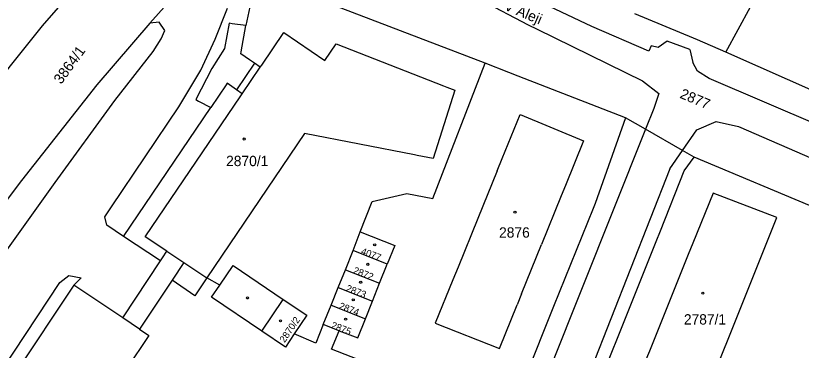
# Model space of a CAD drawing. Extents: x -527335 to -526256, y -1079142 to -1077809.
# Drawn here: x -527020.7 to -526891.4, y -1078778.8 to -1078723.7 of the extents above; entities that cross this region are included whole.
import ezdxf

# ---------------------------------------------------------------- set-up
doc = ezdxf.new("R2010")
doc.units = 0
for name, color, linetype in [('Vrstva 1', 7, 'Continuous'), ('Vrstva 2', 7, 'Continuous'), ('Vrstva 4', 7, 'Continuous'), ('Vrstva 5', 7, 'Continuous'), ('Vrstva 7', 7, 'Continuous')]:
    doc.layers.add(name, color=color, linetype=linetype)

msp = doc.modelspace()

# ---------------------------------------------------------------- linework, layer by layer
at = {"layer": 'Vrstva 1'}
for p, q in [((-526980.85, -1078705.02), (-526998.63, -1078724.92)), ((-526880.94, -1078739.86), (-526903.84, -1078729.73)), ((-526881.96, -1078758.41), (-526909.05, -1078746.98)), ((-526965.19, -1078762.39), (-526964, -1078759.32)), ((-526966.46, -1078765.55), (-526965.19, -1078762.39)), ((-526959.56, -1078764.61), (-526965.19, -1078762.39)), ((-526967.65, -1078768.49), (-526966.46, -1078765.55)), ((-526966.46, -1078765.55), (-526960.82, -1078767.77)), ((-526960.82, -1078767.77), (-526959.56, -1078764.61)), ((-526962, -1078770.71), (-526960.82, -1078767.77)), ((-526968.81, -1078771.4), (-526967.65, -1078768.49)), ((-526967.65, -1078768.49), (-526962, -1078770.71)), ((-526963.17, -1078773.62), (-526962, -1078770.71)), ((-526970.1, -1078774.59), (-526968.81, -1078771.4)), ((-526968.81, -1078771.4), (-526963.17, -1078773.62)), ((-527000.35, -1078775.31), (-527003.07, -1078773.49)), ((-526967.47, -1078775.61), (-526970.1, -1078774.59))]:
    msp.add_line(p, q, dxfattribs=at)
for points in [[(-527072.22, -1078805.43), (-527063.35, -1078791.03), (-527051.39, -1078772.86), (-527021.8, -1078732.24), (-527016.31, -1078725.38), (-526999.22, -1078705.77), (-526979.26, -1078684.5), (-526961.36, -1078666.17), (-526945.34, -1078649.61), (-526932.24, -1078641.62), (-526929.63, -1078639.61), (-526929.14, -1078637.23), (-526930.46, -1078635.68), (-526927.65, -1078633), (-526895.17, -1078602.34)], [(-526943.47, -1078731.53), (-526981.07, -1078717.06), (-526983.77, -1078716), (-526980.85, -1078705.02)], [(-526903.84, -1078729.73), (-526895.72, -1078714.74), (-526874.21, -1078723.48)], [(-526903.84, -1078729.73), (-526908.52, -1078727.66), (-526909.18, -1078727.41), (-526918.83, -1078723.42)], [(-526998.63, -1078724.92), (-527007.36, -1078735.07), (-527019.76, -1078750.86), (-527025.21, -1078757.99), (-527037.26, -1078775.41), (-527043.97, -1078785.5), (-527052.05, -1078797.8), (-527057.33, -1078806.06), (-527064.89, -1078818.36), (-527077.97, -1078839.97), (-527106.45, -1078888.73), (-527179.38, -1079013.92), (-527179.74, -1079015.3)], [(-527060.55, -1078815.59), (-527054.66, -1078805.64), (-527050.43, -1078799.71), (-527048.56, -1078798.89), (-527046.8, -1078797.42), (-527041.37, -1078789.55), (-527032.93, -1078777.37), (-527021.38, -1078761.15), (-527014.2, -1078751.18), (-527004.39, -1078737.66), (-526998.1, -1078729.59), (-526996.78, -1078727.49), (-526996.17, -1078726.12), (-526997.1, -1078724.79), (-526998.63, -1078724.92)], [(-526964, -1078759.32), (-526962.06, -1078754.32), (-526956.34, -1078752.97), (-526952.04, -1078753.82), (-526943.47, -1078731.53)], [(-526920.35, -1078740.55), (-526938, -1078733.66), (-526939.57, -1078733.05), (-526943.47, -1078731.53)], [(-526920.35, -1078740.55), (-526925.32, -1078754.62), (-526925.68, -1078755.46), (-526932.2, -1078771.6), (-526932.87, -1078773.24), (-526939.55, -1078790.03)], [(-526909.05, -1078746.98), (-526910.94, -1078745.91), (-526917.07, -1078742.42), (-526920.35, -1078740.55)], [(-526927.47, -1078791.39), (-526922.47, -1078778.85), (-526921.77, -1078777.09), (-526915.3, -1078760.88), (-526914.6, -1078759.12), (-526910.68, -1078749.28), (-526909.05, -1078746.98)], [(-526920.46, -1078789.01), (-526909.97, -1078793.22), (-526902.69, -1078775.08), (-526895.42, -1078756.95), (-526905.94, -1078752.92), (-526909.26, -1078761.18), (-526910.01, -1078763.03), (-526913.2, -1078770.97), (-526916.41, -1078778.95), (-526917.14, -1078780.77), (-526920.46, -1078789.01)], [(-526964, -1078759.32), (-526958.34, -1078761.55), (-526959.56, -1078764.61)], [(-526980.2, -1078775.69), (-526988.47, -1078770.08), (-526987.11, -1078768.1), (-526989.28, -1078766.89), (-526991.26, -1078769.82), (-526994.98, -1078767.27), (-527000.35, -1078775.31)], [(-527003.07, -1078773.49), (-527011.16, -1078768.09), (-527030.63, -1078797.3), (-527031.8, -1078796.49), (-527033.21, -1078798.48), (-527034.85, -1078797.32), (-527038.02, -1078801.77), (-527036.37, -1078802.94), (-527037.76, -1078804.91), (-527032.72, -1078808.35), (-527034.82, -1078811.52), (-527030.31, -1078814.54), (-527028.85, -1078818), (-527029.14, -1078824.18), (-527031.1, -1078828.29)], [(-526980.2, -1078775.69), (-526976.67, -1078770.44), (-526972.82, -1078773.04), (-526974.87, -1078776.13)], [(-526970.1, -1078774.59), (-526971.32, -1078777.62), (-526974.87, -1078776.13)], [(-526967.47, -1078775.61), (-526964.43, -1078776.78), (-526963.17, -1078773.62)], [(-526974.87, -1078776.13), (-526976.32, -1078778.32), (-526980.2, -1078775.69)], [(-526959.04, -1078782.42), (-526968.73, -1078778.63), (-526967.47, -1078775.61)]]:
    msp.add_lwpolyline(points, dxfattribs=at)
at = {"layer": 'Vrstva 4'}
for p, q in [((-526981.07, -1078717.06), (-526982.85, -1078725.3)), ((-526944.09, -1078721.15), (-526936.39, -1078725.2)), ((-526925.87, -1078725.49), (-526935.89, -1078720.7)), ((-526987.91, -1078727.56), (-526985.84, -1078722.46)), ((-526985.57, -1078724.93), (-526986.36, -1078729.12)), ((-526985.08, -1078725.03), (-526985.57, -1078724.93)), ((-526982.85, -1078725.3), (-526985.08, -1078725.03)), ((-526983.59, -1078729.63), (-526982.85, -1078725.3)), ((-526936.39, -1078725.2), (-526934.89, -1078725.91)), ((-526916.5, -1078729.56), (-526925.87, -1078725.49)), ((-526980.23, -1078731.87), (-526976.56, -1078726.47)), ((-526976.56, -1078726.47), (-526969.86, -1078731.1)), ((-526934.89, -1078725.91), (-526917.53, -1078734.45)), ((-526990.26, -1078732.7), (-526987.91, -1078727.56)), ((-526913.47, -1078727.92), (-526914.99, -1078728.96)), ((-526909.76, -1078729.27), (-526913.47, -1078727.92)), ((-526986.36, -1078729.12), (-526988.44, -1078732.41)), ((-526969.86, -1078731.1), (-526967.95, -1078728.34)), ((-526967.95, -1078728.34), (-526950.3, -1078735.25)), ((-526916.1, -1078728.68), (-526916.5, -1078729.56)), ((-526914.99, -1078728.96), (-526916.1, -1078728.68)), ((-526909.76, -1078729.27), (-526909.25, -1078731.41)), ((-526983.65, -1078730.01), (-526983.59, -1078729.63)), ((-526982.22, -1078730.99), (-526983.65, -1078730.01)), ((-526981.41, -1078731.55), (-526984.39, -1078735.92)), ((-526981.41, -1078731.55), (-526982.22, -1078730.99)), ((-526980.46, -1078732.2), (-526981.41, -1078731.55)), ((-526980.46, -1078732.2), (-526980.23, -1078731.87)), ((-526908.48, -1078732.83), (-526909.25, -1078731.41)), ((-526993.89, -1078738.73), (-526990.26, -1078732.7)), ((-526988.44, -1078732.41), (-526991.09, -1078737.5)), ((-526983.44, -1078736.59), (-526980.46, -1078732.2)), ((-526906.55, -1078734.05), (-526908.48, -1078732.83)), ((-526917.53, -1078734.45), (-526914.87, -1078736.51)), ((-526868.74, -1078750.29), (-526906.55, -1078734.05)), ((-526986.1, -1078735.07), (-526988.62, -1078738.81)), ((-526985.93, -1078734.82), (-526986.1, -1078735.07)), ((-526984.39, -1078735.92), (-526985.93, -1078734.82)), ((-526983.44, -1078736.59), (-526984.39, -1078735.92)), ((-526948.45, -1078735.98), (-526951.99, -1078747.23)), ((-526950.3, -1078735.25), (-526949.75, -1078735.47)), ((-526949.75, -1078735.47), (-526948.45, -1078735.98)), ((-526999.41, -1078760.11), (-526983.66, -1078736.92)), ((-526983.66, -1078736.92), (-526983.44, -1078736.59)), ((-526914.87, -1078736.51), (-526915.7, -1078739)), ((-526991.09, -1078737.5), (-526990.61, -1078737.76)), ((-526990.61, -1078737.76), (-526988.62, -1078738.81)), ((-527004.94, -1078755.16), (-526993.89, -1078738.73)), ((-527002.98, -1078760.08), (-526988.62, -1078738.81)), ((-526915.7, -1078739), (-526917.07, -1078742.42)), ((-526940.65, -1078747.23), (-526937.69, -1078739.96)), ((-526937.69, -1078739.96), (-526927.27, -1078744.31)), ((-526908.59, -1078742.5), (-526905.45, -1078741.15)), ((-526905.45, -1078741.15), (-526901.75, -1078741.96)), ((-526917.07, -1078742.42), (-526963.21, -1078857.88)), ((-526910.94, -1078745.91), (-526908.59, -1078742.5)), ((-526901.75, -1078741.96), (-526853.5, -1078762.97)), ((-526973.18, -1078743.09), (-526989.28, -1078766.89)), ((-526955.07, -1078746.63), (-526973.18, -1078743.09)), ((-526927.27, -1078744.31), (-526930.24, -1078751.65)), ((-526913.03, -1078748.95), (-526910.94, -1078745.91)), ((-526954.63, -1078746.71), (-526955.07, -1078746.63)), ((-526951.99, -1078747.23), (-526954.63, -1078746.71)), ((-526941.46, -1078749.25), (-526940.65, -1078747.23)), ((-526913.03, -1078748.95), (-526959.32, -1078866.11)), ((-526941.46, -1078749.25), (-526944.66, -1078757.1)), ((-526930.24, -1078751.65), (-526930.95, -1078753.4)), ((-526930.95, -1078753.4), (-526934.19, -1078761.41)), ((-527006.04, -1078756.84), (-527004.94, -1078755.16)), ((-527005.71, -1078758.19), (-527006.04, -1078756.84)), ((-526944.66, -1078757.1), (-526947.91, -1078765.12)), ((-527002.98, -1078760.08), (-527005.71, -1078758.19)), ((-526996.88, -1078764.09), (-527002.98, -1078760.08)), ((-526995.84, -1078762.5), (-526999.41, -1078760.11)), ((-526937.48, -1078769.53), (-526934.19, -1078761.41)), ((-526996.55, -1078763.59), (-526995.84, -1078762.5)), ((-526995.84, -1078762.5), (-526993.04, -1078764.37)), ((-527003.07, -1078773.49), (-526996.88, -1078764.09)), ((-526996.88, -1078764.09), (-526996.55, -1078763.59)), ((-526993.04, -1078764.37), (-526994.98, -1078767.27)), ((-526993.04, -1078764.37), (-526989.28, -1078766.89)), ((-526987.11, -1078768.1), (-526984.9, -1078764.87)), ((-526984.9, -1078764.87), (-526976.67, -1078770.44)), ((-526947.91, -1078765.12), (-526948.75, -1078767.19)), ((-527013.46, -1078767.65), (-527011.97, -1078766.48)), ((-527011.97, -1078766.48), (-527009.96, -1078766.89)), ((-527009.96, -1078766.89), (-527011.16, -1078768.09)), ((-527026.13, -1078786.78), (-527013.46, -1078767.65)), ((-526948.75, -1078767.19), (-526951.66, -1078774.34)), ((-526937.48, -1078769.53), (-526938.2, -1078771.31)), ((-526941.11, -1078778.51), (-526938.2, -1078771.31)), ((-526951.66, -1078774.34), (-526941.11, -1078778.51)), ((-527000.35, -1078775.31), (-526998.79, -1078776.35)), ((-526998.79, -1078776.35), (-527003.65, -1078783.54))]:
    msp.add_line(p, q, dxfattribs=at)
at = {"layer": 'Vrstva 5'}
for centre in [(-526983.12, -1078744.02), (-526938.54, -1078756.06), (-526961.63, -1078761.44), (-526962.75, -1078764.66), (-526963.93, -1078767.61), (-526907.61, -1078769.4), (-526982.58, -1078770.19), (-526965.16, -1078770.49), (-526966.41, -1078773.7), (-526977.13, -1078773.97)]:
    msp.add_circle(centre, 0.175, dxfattribs=at)

# ---------------------------------------------------------------- texts
at = {"layer": 'Vrstva 2'}
for s, height, rotation, p in [('3864/1', 1.7, 54, (-527013.24, -1078735.1)), ('2877', 1.7, 337, (-526911.53, -1078737.19)), ('4077', 1.14, 339, (-526964, -1078762.93)), ('2872', 1.14, 339, (-526965.27, -1078766.09)), ('2873', 1.14, 339, (-526966.46, -1078769.03)), ('2874', 1.14, 339, (-526967.62, -1078771.94)), ('2870/2', 1.14, 56, (-526976.45, -1078777.65)), ('2875', 1.14, 339, (-526968.91, -1078775.13))]:
    msp.add_text(s, height=height, rotation=rotation, dxfattribs=at).set_placement(p)
for s, p in [('2870/1', (-526986.09, -1078748.48)), ('2876', (-526941.16, -1078760.26)), ('2787/1', (-526910.74, -1078774.57))]:
    msp.add_text(s, height=1.7, dxfattribs=at).set_placement(p)
at = {"layer": 'Vrstva 7'}
msp.add_text('V Aleji', height=1.7, rotation=337, dxfattribs=at).set_placement((-526940.44, -1078722.67))

doc.saveas('drawing.dxf')
